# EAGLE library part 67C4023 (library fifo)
FIFO
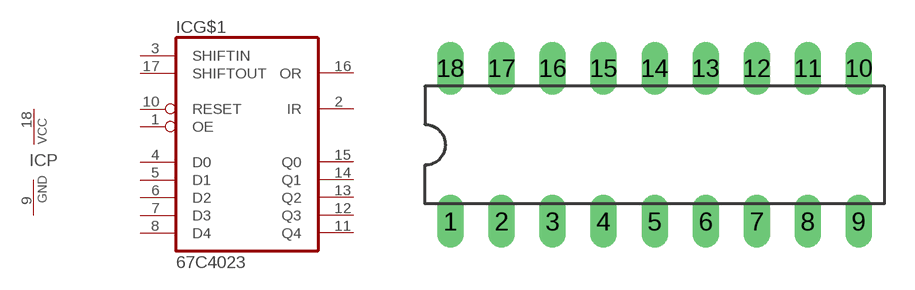
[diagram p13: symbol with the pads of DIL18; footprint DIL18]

Designator prefix IC; gates G$1=67C4023 P=PWRN

## 67C4023 (OC_FARNELL: unknown; OC_NEWARK: unknown)  [DIL18]
1  G$1:OE  in
2  G$1:IR  out
3  G$1:SHIFTIN  in
4  G$1:D0  in
5  G$1:D1  in
6  G$1:D2  in
7  G$1:D3  in
8  G$1:D4  in
9  P:GND  pwr
10  G$1:RESET  in
11  G$1:Q4  hiz
12  G$1:Q3  hiz
13  G$1:Q2  hiz
14  G$1:Q1  hiz
15  G$1:Q0  hiz
16  G$1:OR  out
17  G$1:SHIFTOUT  in
18  P:VCC  pwr

## Footprint DIL18 (pad centres in mm)
Dual In Line Package
drill 0.813 long: 1 -10.16,-3.81; 2 -7.62,-3.81; 3 -5.08,-3.81; 4 -2.54,-3.81; 5 0,-3.81; 6 2.54,-3.81; 7 5.08,-3.81; 8 7.62,-3.81; 9 10.16,-3.81; 10 10.16,3.81; 11 7.62,3.81; 12 5.08,3.81; 13 2.54,3.81; 14 0,3.81; 15 -2.54,3.81; 16 -5.08,3.81; 17 -7.62,3.81; 18 -10.16,3.81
